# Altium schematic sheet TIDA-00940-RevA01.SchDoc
size 431 x 279 mm; Date: Not shown in title block; ApprovedBy: Not shown in title block; CheckedBy: Not shown in title block; Author: Not shown in title block; CompanyName: Not shown in title block; Engineer: Not shown in title block; Organization: Not shown in title block; Address1: Not shown in title block; Address2: Not shown in title block; Address3: Not shown in title block; Address4: Not shown in title block; DocumentNumber: 1; Revision: Use project parameter SCH_Rev; SheetNumber: 2; SheetTotal: 3; PageSetup: Record=PageOptions¦CenterHorizontal=True¦CenterVertical=True¦PrintScale=1.00¦XCorrection=1.00¦YCorrection=1.00¦PrintKind=0¦BorderSize=5000000¦LeftOffset=0¦BottomOffset=0¦Orientation=2¦PaperLength=1000¦PaperWidth=1000¦Scale=100¦PaperSource=15¦PrintQuality=600¦MediaType=1¦DitherType=10¦PaperKind=Letter¦PrintScaleMode=1
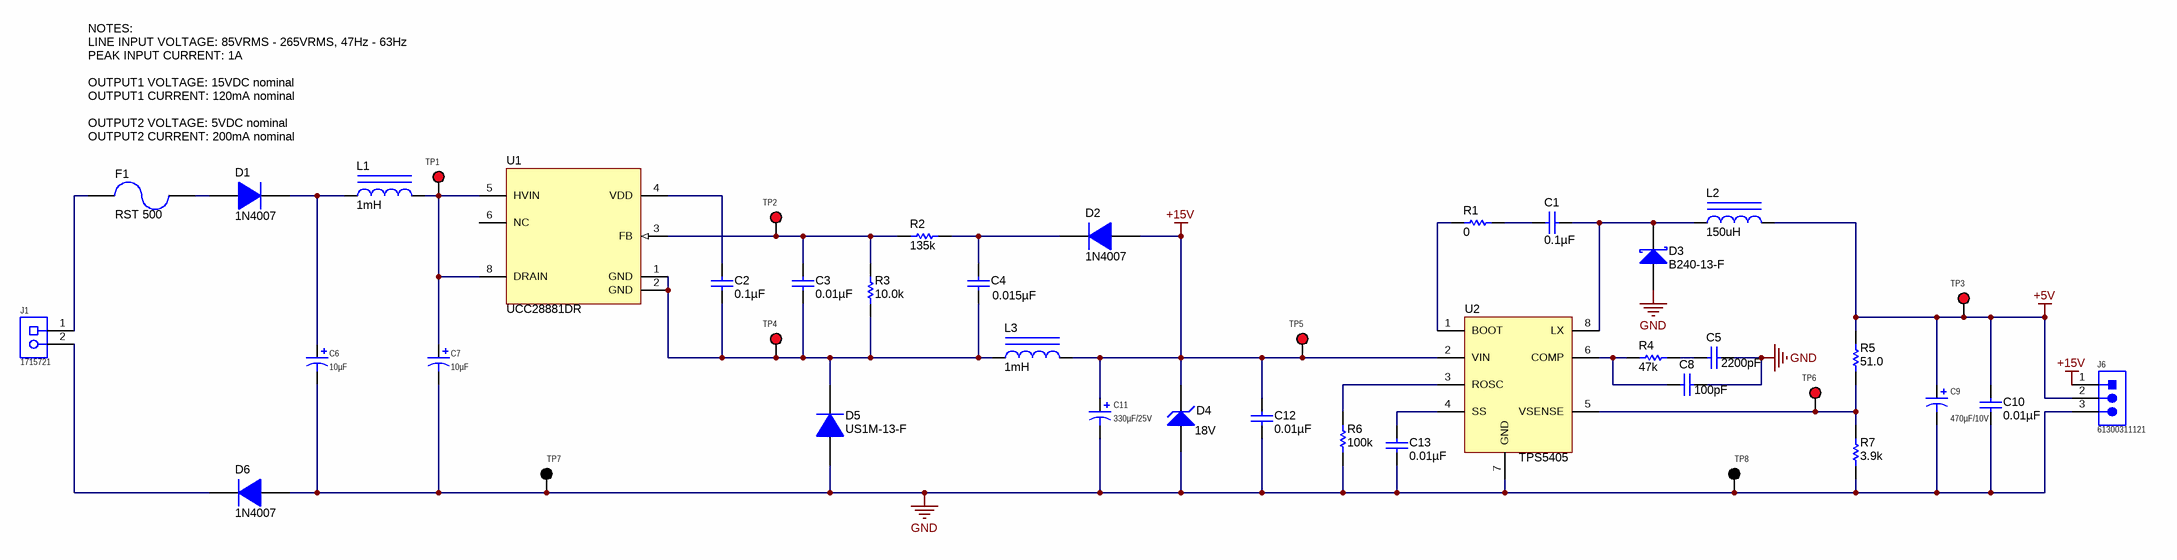
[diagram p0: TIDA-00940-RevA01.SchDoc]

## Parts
C1  ValueDisplayed: 0.1µF  [0603]  (hidden comment: C1608X7R1H104K080AA)
C2  ValueDisplayed: 0.1µF  [0603]  (hidden comment: C1608X7R1H104K080AA)
C3  ValueDisplayed: 0.01µF  [0603]  (hidden comment: C1608X7R1H103K)
C4  ValueDisplayed: 0.015µF  [0603]  (hidden comment: C1608X7R1H153K080AA)
C5  ValueDisplayed: 2200pF  [0603]  (hidden comment: 06031C222JAT2A)
C6  ValueDisplayed: 10µF  [CY_1000x1600]  (hidden comment: UCY2G100MPD1TD)
C7  ValueDisplayed: 10µF  [CY_1000x1600]  (hidden comment: UCY2G100MPD1TD)
C8  ValueDisplayed: 100pF  [0603]  (hidden comment: 06035A101FAT2A)
C9  ValueDisplayed: 470µF/10V  [E/P3.2/D8]  (hidden comment: UPW1A471MPD)
C10  ValueDisplayed: 0.01µF  [0603]  (hidden comment: C1608X7R1H103K)
C11  ValueDisplayed: 330µF/25V  [E5/10]  (hidden comment: UPW1E331MPD)
C12  ValueDisplayed: 0.01µF  [0603]  (hidden comment: C1608X7R1H103K)
C13  ValueDisplayed: 0.01µF  [0603]  (hidden comment: C1608X7R1H103K)
D1  1N4007  [DO-41]
D2  1N4007  [DO-41]
D3  B240-13-F  [SMB]
D4  value 18V  [SOD-123]  (hidden comment: MMSZ4705T1G)
D5  US1M-13-F  [SMA]
D6  1N4007  [DO-41]
F1  RST 500  [Fuse_RST]
J1  1715721  [PhoenixContact_1715721]
J6  61300311121  [WURTH_61300311121]
L1  ValueDisplayed: 1mH  [5800]  (hidden comment: 5800-102-RC)
L2  ValueDisplayed: 150uH  [Inductor-P5D8]  (hidden comment: RL622-151K-RC)
L3  ValueDisplayed: 1mH  [WE-TIS-1111]  (hidden comment: 7447471102)
R1  ValueDisplayed: 0  [0603]  (hidden comment: CRCW06030000Z0EA)
R2  ValueDisplayed: 135k  [0603]  (hidden comment: RT0603DRE07135KL)
R3  ValueDisplayed: 10.0k  [0603]  (hidden comment: RC0603FR-0710KL)
R4  ValueDisplayed: 47k  [0603]  (hidden comment: CRCW060347K0JNEA)
R5  ValueDisplayed: 51.0  [0603]  (hidden comment: RC0603FR-0751RL)
R6  ValueDisplayed: 100k  [0603]  (hidden comment: CRCW0603100KFKEA)
R7  ValueDisplayed: 3.9k  [0603]  (hidden comment: CRCW06033K90JNEA)
TP1  5000  [Keystone5000]  (value not drawn)
TP2  5000  [Keystone5000]  (value not drawn)
TP3  5000  [Keystone5000]  (value not drawn)
TP4  5000  [Keystone5000]  (value not drawn)
TP5  5000  [Keystone5000]  (value not drawn)
TP6  5000  [Keystone5000]  (value not drawn)
TP7  5001  [Keystone5001]  (value not drawn)
TP8  5001  [Keystone5001]  (value not drawn)
U1  UCC28881DR  [D0007A_N]
U2  TPS5405  [SO-G8/E2.5]

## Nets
+5V: C9.1(+) C10.1 J6.2 L2.2 R5.2 TP3.1
+15V: C11.1(+) C12.1 D2.2(A) D4.1(K) J6.1 L3.2 TP5.1 U2.2(VIN)
GND: C5.1 C6.2(-) C7.2(-) C8.1 C9.2(-) C10.2 C11.2(-) C12.2 C13.2 D3.2(A) D4.2(A) D5.2(A) D6.2(A) J6.3 R6.1 R7.1 TP7.1 TP8.1 U2.7(GND)
NetC1_1: C1.1 R1.2
NetC1_2: C1.2 D3.1(K) L2.1 U2.8(LX)
NetC2_1: C2.1 U1.4(VDD)
NetC2_2: C2.2 C3.2 C4.2 D5.1(K) L3.1 R3.1 TP4.1 U1.1(GND) U1.2(GND)
NetC3_1: C3.1 R2.1 R3.2 TP2.1 U1.3(FB)
NetC4_1: C4.1 D2.1(K) R2.2
NetC5_2: C5.2 R4.2
NetC6_1: C6.1(+) D1.1(K) L1.1
NetC7_1: C7.1(+) L1.2 TP1.1 U1.5(HVIN) U1.8(DRAIN)
NetC8_2: C8.2 R4.1 U2.6(COMP)
NetC13_1: C13.1 U2.4(SS)
NetD1_2: D1.2(A) F1.1
NetD6_1: D6.1(K) J1.2
NetF1_2: F1.2 J1.1
NetR1_1: R1.1 U2.1(BOOT)
NetR5_1: R5.1 R7.2 TP6.1 U2.5(VSENSE)
NetR6_2: R6.2 U2.3(ROSC)

Not connected (* = marked no-connect by the designer): U1 6(NC)

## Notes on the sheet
- NOTES:
  LINE INPUT VOLTAGE: 85VRMS - 265VRMS, 47Hz - 63Hz
  PEAK INPUT CURRENT: 1A
  OUTPUT1 VOLTAGE: 15VDC nominal
  OUTPUT1 CURRENT: 120mA nominal
  OUTPUT2 VOLTAGE: 5VDC nominal
  OUTPUT2 CURRENT: 200mA nominal

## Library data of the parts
C1 C2 = C1608X7R1H104K080AA: CAP, CERM, 0.1 µF, 50 V, +/- 10%, X7R, 0603; Manufacturer: TDK; Polarized: N; CompType: Capacitor; Value: 0.1uF; U/M: EA; Cap_F: 0.0000001; Tolerance_%: 10; Value1: Unknown; VDC_V: 50; Value2: 50V; TaMin_C: -55; TaMax_C: 125; AEC Category: Q200
C3 C10 C12 C13 = C1608X7R1H103K: CAP, CERM, 0.01 µF, 50 V, +/- 10%, X7R, 0603; Manufacturer: TDK; Polarized: N; CompType: Capacitor; Value: 0.01uF; U/M: EA; Cap_F: 0.00000001; Tolerance_%: 10; ESR_ohm: 0.0539; Value1: 0.0539 ohm; VDC_V: 50; Value2: 50V; TaMin_C: -55; TaMax_C: 125; AEC Category: Q200
C4 = C1608X7R1H153K080AA: CAP, CERM, 0.015 µF, 50 V, +/- 10%, X7R, AEC-Q200 Grade 1, 0603; Manufacturer: TDK; Polarized: N; CompType: Capacitor; Value: 0.015uF; U/M: EA; Cap_F: 0.000000015; Tolerance_%: 10; Value1: Unknown; VDC_V: 50; Value2: 50V; TaMin_C: -55; TaMax_C: 125; AEC Category: Q200; AEC Qualified: Y; AEC Grade: 1
C5 = 06031C222JAT2A: CAP, CERM, 2200 pF, 100 V, +/- 5%, X7R, 0603; Manufacturer: AVX; Polarized: N; CompType: Capacitor; Value: 2200pF; U/M: EA; Cap_F: 0.0000000022; Tolerance_%: 5; ESR_ohm: 0.192; Value1: 0.192 ohm; VDC_V: 100; Value2: 100V; TaMin_C: -55; TaMax_C: 125; AEC Category: Q200
C6 C7 = UCY2G100MPD1TD: CAP, AL, 10 µF, 400 V, +/- 20%,  ohm, TH; Manufacturer: Nichicon; Polarized: Y; CompType: Capacitor; Value: 10uF; U/M: EA; Cap_F: 0.00001; Tolerance_%: 20; Value1: Unknown; VDC_V: 400; Value2: 400V; IRMS_A: 0.15; TaMin_C: -40; TaMax_C: 105; Cap_Case: 10x16mm
C8 = 06035A101FAT2A: CAP, CERM, 100 pF, 50 V, +/- 1%, C0G/NP0, 0603; Manufacturer: AVX; Polarized: N; CompType: Capacitor; Value: 100pF; U/M: EA; Cap_F: 0.0000000001; Tolerance_%: 1; Value1: Unknown; VDC_V: 50; Value2: 50V; TaMin_C: -55; TaMax_C: 125; AEC Category: Q200
C9 = UVR1V100MDD1TA: CAP, AL, 10 µF, 35 V, +/- 20%, TH; Manufacturer: Nichicon; Polarized: Y; CompType: Capacitor; Value: 10uF; U/M: EA; Cap_F: 0.00001; Tolerance_%: 20; Value1: Unknown; VDC_V: 35; Value2: 35V; TaMin_C: -40; TaMax_C: 85; Cap_Case: 5x11
C11 = UVR1V100MDD1TA: CAP, AL, 330 µF, 25 V, +/- 20%, TH; Manufacturer: Nichicon; Polarized: Y; CompType: Capacitor; Value: 10uF; U/M: EA; Cap_F: 0.00001; Tolerance_%: 20; Value1: Unknown; VDC_V: 35; Value2: 35V; TaMin_C: -40; TaMax_C: 85; Cap_Case: 5x11
D1 D2 D6 = 1N4007: Diode, P-N, 1000 V, 1 A, TH; Manufacturer: Fairchild Semiconductor; U/M: EA; Vf_V: 1.1; Value: 1000V; Value1: 1A; Value2: 1.1V; Io_A: 1; Vr_V: 1000; TJmax_C: 175; RJC_CperW: 50; AEC Category: Q101
D3 = B240-13-F: Diode, Schottky, 40 V, 2 A, SMB; Manufacturer: Diodes Inc.; U/M: EA; Vf_V: 0.5; Value: 40V; Value1: 2A; Value2: 0.5V; Io_A: 2; Vr_V: 40; TJmax_C: 150; RJC_CperW: 20; AEC Category: Q101
D4 = MMSZ4705T1G: Diode, Zener, 18 V, 500 mW, SOD-123; Manufacturer: ON Semiconductor; SymbolCreator: a0412235; U/M: EA; Power_W: 0.5; Vz_V: 18; Value1: 0.5W; RJA_CperW: 340; AEC Category: Q101
D5 = US1M-13-F: Diode, Ultrafast, 1000 V, 1 A, SMA; Manufacturer: Diodes Inc.; U/M: EA; Vf_V: 1.7; Value: 1000V; Value1: 1A; Value2: 1.7V; Io_A: 1; Vr_V: 1000; TJmax_C: 150; RJC_CperW: 30; AEC Category: Q101
F1 = RST 500: Fuse, 0.5 A, 250VAC/VDC, TH; Manufacturer: Bel Fuse; VDC_V: 250; Irating_A: 0.5; Rtyp_Ohm: 0.18; MeltingTyp: 1.7
J1 = 1715721: Conn Term Block, 2POS, 5.08mm, TH; Manufacturer: Phoenix Contact; SymbolCreator: a0412235; CompType: Terminal Block; U/M: EA; Value: 2x1
J6 = 61300311121: Header, 2.54 mm, 3x1, Gold, TH; Manufacturer: Wurth Elektronik; SymbolCreator: a0799628; U/M: EA
L1 = 5800-102-RC: Inductor, Wirewound, Ferrite, 1 mH, 0.2 A, 2.3 ohm, TH; Manufacturer: Bourns; Value: 1mH; Ind_H: 1.0E-3; Imax_A: 0.2; Irms: 0.2A @ 35C rise; Isat: 0.4A @ 10% inductance drop; DCR_ohm: 2.3; Value1: 2.3 ohm; Value2: 0.2A; AEC Category: Q200
L2 = 7447471102: Inductor, Wirewound, Ferrite, 150uH, 0.75 A, 1.2 ohm, TH; Manufacturer: BOURNS; Value: 1mH; Ind_H: 1.0E-3; Imax_A: 0.4; Irms: 0.6A @ 40C rise; Isat: 0.4A @ 10% inductance drop; DCR_ohm: 1.2; Value1: 1.2 ohm; Value2: 0.4A; AEC Category: Q200; AEC Qualified: N
L3 = 7447471102: Inductor, Wirewound, Ferrite, 1 mH, 0.4 A, 1.2 ohm, TH; Manufacturer: Wurth Elektronik; Value: 1mH; Ind_H: 1.0E-3; Imax_A: 0.4; Irms: 0.6A @ 40C rise; Isat: 0.4A @ 10% inductance drop; DCR_ohm: 1.2; Value1: 1.2 ohm; Value2: 0.4A; AEC Category: Q200; AEC Qualified: N
R1 = CRCW06030000Z0EA: RES, 0, 5%, 0.1 W, 0603; Manufacturer: Vishay-Dale; CompType: Resistor; Value: 0; Value_Code: 0000; Tolerance_%: 5; Power_W: 0.1; Value2: 0.1W; VDC_V: 75; TempCo: 200 ppm/C; EIA_Code: E24; U/M: EA; AEC Category: Q200
R2 = RT0603DRE07135KL: RES, 135 k, 0.5%, 0.1 W, 0603; Manufacturer: Yageo America; CompType: Resistor; Value: 135k; Res_ohm: 135000; Tolerance_%: 0.5; Power_W: 0.1; Value2: 0.1W; VDC_V: 75; TempCo: 50 ppm/C; EIA_Code: E192; U/M: EA; AEC Category: Q200
R3 = RC0603FR-0710KL: RES, 10.0 k, 1%, 0.1 W, 0603; Manufacturer: Yageo America; CompType: Resistor; Value: 10.0k; Res_ohm: 10000; Value_Code: 10k0; Tolerance_%: 1; Power_W: 0.1; Value2: 0.1W; VDC_V: 150; TempCo: 200 ppm/C; EIA_Code: E96; U/M: EA; AEC Category: Q200
R4 = CRCW060347K0JNEA: RES, 47 k, 5%, 0.1 W, 0603; Manufacturer: Vishay-Dale; CompType: Resistor; Value: 47k; Res_ohm: 47000; Value_Code: 47k0; Tolerance_%: 5; Power_W: 0.1; Value2: 0.1W; VDC_V: 75; TempCo: 200 ppm/C; EIA_Code: E24; U/M: EA; AEC Category: Q200
R5 = RC0603FR-0751RL: RES, 51.0, 1%, 0.1 W, 0603; Manufacturer: Yageo America; CompType: Resistor; Value: 51.0; Res_ohm: 51; Value_Code: 51R0; Tolerance_%: 1; Power_W: 0.1; Value2: 0.1W; VDC_V: 150; TempCo: 200 ppm/C; U/M: EA; AEC Category: Q200
R6 = CRCW0603100KFKEA: RES, 100 k, 1%, 0.1 W, 0603; Manufacturer: Vishay-Dale; CompType: Resistor; Value: 100k; Res_ohm: 100000; Tolerance_%: 1; Power_W: 0.1; Value2: 0.1W; VDC_V: 75; TempCo: 100 ppm/C; EIA_Code: E96; U/M: EA; AEC Category: Q200
R7 = CRCW06033K90JNEA: RES, 3.9 k, 5%, 0.1 W, 0603; Manufacturer: Vishay-Dale; CompType: Resistor; Value: 3.9k; Res_ohm: 3900; Value_Code: 3k90; Tolerance_%: 5; Power_W: 0.1; Value2: 0.1W; VDC_V: 75; TempCo: 200 ppm/C; EIA_Code: E24; U/M: EA; AEC Category: Q200
TP1-TP6 = 5000: Test Point, Miniature, Red, TH; Manufacturer: Keystone; CompType: Test Point Loop; U/M: EA
TP7 TP8 = 5001: Test Point, Miniature, Black, TH; Manufacturer: Keystone; CompType: Test Point Loop; U/M: EA
U1 = UCC28881DR: 700-V Lowest Quiescent Current Off-Line Switcher, D0007A; Manufacturer: Texas Instruments; SymbolCreator: a0411947; CompType: IC; U/M: EA
U2 = TPS5405: Manufacturer: Used in BOM report; SymbolVersion: use current date i.e. 2008-05-20; SymbolCreator: Use a-id; CompType: Used in some BOM reports.  Useful for finding later.; U/M: EA, IN, or GM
